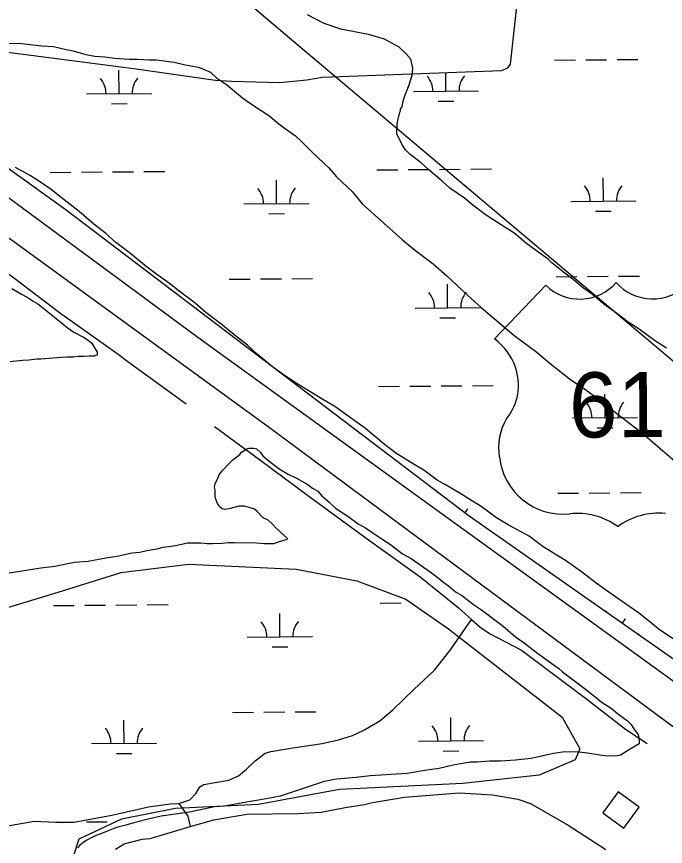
# Model space of a CAD drawing. Extents: x 3540316 to 3578335, y 553172 to 578787.
# Drawn here: x 3561395 to 3562392, y 561755 to 563030 of the extents above; entities that cross this region are included whole.
import ezdxf

# ---------------------------------------------------------------- set-up
doc = ezdxf.new("R2010")
doc.units = 0
for name, color, linetype in [('V-BLDG-OTLN', 7, 'Continuous'), ('V-ROAD-CNTR', 7, 'Continuous'), ('V-ROAD-IDEN', 7, 'Continuous'), ('V-SITE-VEGE', 7, 'Continuous'), ('V-TOPO-SHOR', 7, 'Continuous'), ('V-UTIL-LINE', 7, 'Continuous'), ('V-WETL-SWMP', 7, 'Continuous')]:
    doc.layers.add(name, color=color, linetype=linetype)

msp = doc.modelspace()

# ---------------------------------------------------------------- linework, layer by layer
at = {"layer": 'V-BLDG-OTLN'}
msp.add_lwpolyline([(3562351.7, 561815.5), (3562319.4, 561839), (3562295.8, 561806.7), (3562328.1, 561783.2)], close=True, dxfattribs=at)
at = {"layer": 'V-ROAD-CNTR'}
for points in [[(3562447.9, 561906.3), (3561783.8, 562398.2), (3561237.9, 562795), (3560747.4, 563166.4), (3559829.5, 563849.1), (3558932.4, 564513), (3557712.7, 565416.8), (3556649.6, 566203.3), (3555719, 566897), (3553740.9, 568356)], [(3561107.6, 562954.7), (3561673.7, 562537.4)], [(3561673.7, 562537.4), (3562657, 561826.3), (3562970.4, 561585), (3563229, 561375.2), (3563431.3, 561200.6), (3563553.8, 561106), (3563686, 560983.7)]]:
    msp.add_lwpolyline(points, dxfattribs=at)
at = {"layer": 'V-ROAD-IDEN'}
for q in [(3562208, 562617), (3562208, 562617), (3562129.5, 562534.7)]:
    msp.add_line((3562129.5, 562534.7), q, dxfattribs=at)
for centre, major_axis, start_param, end_param in [((3562260.2, 562670.8), (0.6, -75), 5.502702, 7.121811), ((3562260.2, 562670.8), (0.6, -75), 5.502702, 7.121811), ((3562372.2, 562671), (-0.6, 75), 2.291842, 3.917604), ((3562372.2, 562671), (-0.6, 75), 2.291842, 3.917604), ((3562074.7, 562460.5), (-0.7, 92.2), 5.045266, 5.638568), ((3562074.7, 562460.5), (-0.7, 92.2), 5.045266, 5.638568), ((3562084.8, 562463.7), (-0.6, 81.6), 4.021008, 5.049788), ((3562084.8, 562463.7), (-0.6, 81.6), 4.021008, 5.049788), ((3562221.9, 562367.6), (0.7, -86.5), 4.163028, 4.868958), ((3562221.9, 562367.6), (0.7, -86.5), 4.163028, 4.868958), ((3562234.8, 562364.2), (-0.8, 98.8), 1.672766, 3.238327), ((3562234.8, 562364.2), (-0.8, 98.8), 1.672766, 3.238327), ((3562256.7, 562161), (-0.8, 105.6), 5.646836, 6.385311), ((3562256.7, 562161), (-0.8, 105.6), 5.646836, 6.385311), ((3562381.4, 562161.3), (0.8, -105.6), 3.034929, 3.773404), ((3562381.4, 562161.3), (0.8, -105.6), 3.034929, 3.773404)]:
    msp.add_ellipse(centre, major_axis=major_axis, ratio=0.99789, start_param=start_param, end_param=end_param, dxfattribs=at)
at = {"layer": 'V-SITE-VEGE'}
for points in [[(3561985.2, 562884.9), (3561985.2, 562888.1), (3561987.4, 562891.3), (3561988.5, 562897.8), (3561990.7, 562905.3), (3561998.4, 562924.6), (3562002.8, 562939.6), (3562004, 562950.4), (3562000.9, 562964.4), (3561993.4, 562973), (3561982.7, 562982.8), (3561960.2, 562994.8), (3561937.7, 563001.4), (3561893.6, 563010.4), (3561867.9, 563019.2), (3561842.1, 563032.3)], [(3561327.6, 562988.8), (3561402.9, 562988.2), (3561434.1, 562984.8), (3561452.3, 562983.6), (3561471.7, 562979.1), (3561482.4, 562976.9), (3561501.7, 562971.4), (3561515.7, 562969.1), (3561530.8, 562967.9), (3561545.8, 562965.6), (3561568.4, 562964.4), (3561581.3, 562964.3), (3561599.6, 562963.1), (3561610.3, 562963), (3561637.2, 562959.6), (3561652.2, 562956.2), (3561663, 562954), (3561674.8, 562951.8), (3561683.4, 562948.5), (3561693, 562944.1), (3561702.6, 562935.4), (3561717.6, 562925.6), (3561742.2, 562905), (3561752.9, 562897.4), (3561771.1, 562885.4), (3561782.9, 562877.8), (3561797.9, 562864.8), (3561808.6, 562857.2), (3561823.5, 562846.3), (3561833.2, 562837.6), (3561848.1, 562822.5), (3561858.8, 562812.7), (3561874.8, 562797.5), (3561886.5, 562783.4), (3561911.1, 562760.7), (3561926, 562742.3), (3561988, 562686.9), (3562006.2, 562671.7), (3562035.1, 562650), (3562056.4, 562631.6), (3562088.5, 562601.2), (3562108.8, 562582.7), (3562159, 562540.4), (3562194.3, 562514.3), (3562214.7, 562497), (3562246.7, 562472), (3562269.2, 562456.8), (3562293.8, 562438.3), (3562319.5, 562418.7)], [(3562393.4, 562520.4), (3562375.2, 562532.3), (3562351.7, 562549.7), (3562334.5, 562560.6), (3562313.1, 562576.9), (3562299.2, 562586.7), (3562280, 562603), (3562266.1, 562612.8), (3562250, 562625.8), (3562237.2, 562635.6), (3562218, 562650.8), (3562211.6, 562657.3), (3562184.8, 562676.8), (3562178.4, 562681.2), (3562159.1, 562697.5), (3562145.2, 562706.2), (3562127, 562718.2), (3562115.2, 562725.8), (3562096, 562739.9), (3562083.2, 562750.8), (3562060.7, 562766), (3562048.9, 562776.8), (3562028.6, 562794.2), (3562016.9, 562805), (3561999.8, 562818.1), (3561992.3, 562825.7), (3561988, 562832.2), (3561983.8, 562839.7), (3561979.5, 562849.4), (3561979.7, 562864.5), (3561980.8, 562869.9), (3561984.1, 562882.7), (3561985.2, 562884.9)], [(3561429.3, 562777.2), (3561415.4, 562785.9), (3561393.9, 562797.9)], [(3562405.1, 562072.8), (3562382.6, 562088), (3562367.7, 562099.9), (3562350.6, 562114), (3562317.4, 562136.9), (3562285.3, 562159.7), (3562262.8, 562177.1), (3562238.2, 562194.5), (3562203.9, 562215.2), (3562182.5, 562231.5), (3562150.4, 562248.9), (3562132.2, 562259.8), (3562108.7, 562277.2), (3562091.5, 562288.1), (3562077.6, 562296.8), (3562055.1, 562309.9), (3562041.2, 562317.5), (3562020.9, 562332.8), (3562005.9, 562341.5), (3561978, 562358.9), (3561959.8, 562373), (3561931, 562396.9), (3561911.7, 562411), (3561883.9, 562430.6), (3561865.7, 562441.5), (3561849.6, 562451.3), (3561825, 562466.5), (3561806.8, 562478.5), (3561788.6, 562491.6), (3561765.1, 562511.1), (3561750.1, 562525.2), (3561726.6, 562543.7), (3561711.6, 562555.6), (3561686, 562575.2), (3561669.9, 562589.3), (3561645.3, 562607.7), (3561630.3, 562619.7), (3561608.9, 562634.9), (3561591.8, 562647.9), (3561568.3, 562667.5), (3561548, 562682.7), (3561532, 562696.8), (3561513.8, 562710.9), (3561491.3, 562730.5), (3561459.2, 562755.4), (3561448.6, 562764.1), (3561429.3, 562777.2)], [(3561388, 562612.1), (3561402.7, 562603.3), (3561411.9, 562598.6), (3561421, 562592.4), (3561428.2, 562588.3), (3561439.9, 562579.5), (3561448.5, 562572.2), (3561463.7, 562559.9), (3561472.9, 562552.1), (3561483.1, 562544.9), (3561498.3, 562537.1), (3561503.9, 562533.5), (3561510.5, 562528.8), (3561519.1, 562514.5), (3561519.1, 562509.9), (3561516.5, 562508.9), (3561514.5, 562507.9), (3561506.8, 562507.9), (3561499.1, 562507.5), (3561489.4, 562507.5), (3561482.8, 562506.6), (3561472.5, 562506.6), (3561463.8, 562506.2), (3561444.9, 562504.3), (3561432.6, 562503.4), (3561426.5, 562503.4), (3561414.2, 562502), (3561404.5, 562501.5), (3561385.6, 562499.6)], [(3562319.5, 562418.7), (3562356.9, 562389.4), (3562413.6, 562340.6)], [(3561736.7, 562277.8), (3561731.3, 562276.1), (3561721.5, 562273.5), (3561715.3, 562272.7), (3561711.7, 562273.6), (3561707.3, 562276.3), (3561705.5, 562279.8), (3561703.8, 562281.6), (3561702.9, 562284.3), (3561700.3, 562291.5), (3561700.4, 562302.1), (3561699.5, 562306.6), (3561700.5, 562312.8), (3561703.2, 562318.1), (3561706.8, 562327), (3561712.2, 562333.2), (3561721.1, 562342.9), (3561727.4, 562349.1), (3561738.2, 562357), (3561740.9, 562360.6), (3561748.9, 562365.8), (3561752.5, 562366.7), (3561759.6, 562366.7), (3561764, 562365.7), (3561770.2, 562360.3), (3561773.7, 562355), (3561780.8, 562348.7), (3561785.2, 562345.1), (3561794.1, 562338.8), (3561798.5, 562335.2), (3561812.7, 562327.1), (3561825.1, 562320.8), (3561842.8, 562310.9), (3561849.9, 562305.5), (3561857.9, 562301), (3561864.1, 562293.8), (3561875.6, 562283.9), (3561885.3, 562274.9), (3561903.9, 562262.3), (3561919.8, 562250.6), (3561931.3, 562244.3), (3561941.1, 562238), (3561957.9, 562226.3), (3561969.4, 562219.1), (3561988, 562204.7), (3562001.3, 562197.5), (3562030.5, 562176.8), (3562040.2, 562169.6), (3562051.7, 562160.7), (3562058.8, 562155.3), (3562069.4, 562146.3), (3562080.1, 562140), (3562096.9, 562126.5)], [(3561380.8, 562174.6), (3561432.5, 562183.1), (3561453.9, 562185.6), (3561484.2, 562191.6), (3561505.5, 562193.2), (3561532.3, 562198.4), (3561550.1, 562200.9), (3561572.4, 562206.1), (3561584.8, 562206.9), (3561595.5, 562209.5), (3561610.7, 562212), (3561620.5, 562214.6), (3561633, 562216.3), (3561641.9, 562218), (3561653.5, 562220.6), (3561657.9, 562221.5), (3561678.4, 562221.3), (3561688.2, 562220.3), (3561696.2, 562220.3), (3561711.3, 562221.1), (3561720.2, 562221.9), (3561730, 562221.8), (3561763.8, 562221.6), (3561775.4, 562220.6), (3561790.5, 562220.5), (3561797.7, 562223.1), (3561805.7, 562225.7), (3561809.3, 562226.6), (3561811.9, 562227.4), (3561793.4, 562244.5), (3561788.1, 562250.7), (3561781.9, 562256.1), (3561773.9, 562259.8), (3561765.1, 562269.6), (3561760.7, 562273.2), (3561752.7, 562275.9), (3561745.6, 562277.8), (3561736.7, 562277.8)], [(3562096.9, 562126.5), (3562109.3, 562118.4), (3562142.9, 562093.2), (3562161.5, 562077.1), (3562174.8, 562068.1), (3562193.3, 562053.7), (3562206.6, 562043.8), (3562227.9, 562028.5), (3562234, 562023.1), (3562254.4, 562007.8), (3562266.8, 561998), (3562283.6, 561985.4), (3562293.3, 561977.3), (3562308.4, 561967.4), (3562318.1, 561959.3), (3562327.9, 561952.1), (3562333.2, 561948.5), (3562339.3, 561942.2), (3562344.6, 561934.2), (3562349.9, 561927), (3562350.8, 561922.6), (3562351.6, 561915.4), (3562351.6, 561912.8), (3562339.1, 561905.7), (3562323, 561895.2), (3562317.6, 561894.3), (3562302.5, 561893.6), (3562290.9, 561895.4), (3562272.3, 561898.2), (3562258.9, 561900.1), (3562237.6, 561900.3), (3562219.8, 561897.7), (3562185.9, 561890), (3562161.8, 561887.5), (3562138.7, 561885.9), (3562121.8, 561886), (3562102.2, 561884.4), (3562092.4, 561884.5), (3562077.2, 561881.9), (3562065.7, 561880.2), (3562044.3, 561875), (3562025.6, 561872.5), (3561995.3, 561867.4), (3561938.3, 561863.4), (3561916.9, 561860.9), (3561886.6, 561858.4), (3561867.9, 561855), (3561849.2, 561848.9), (3561818.8, 561838.5), (3561800.1, 561832.4), (3561778.7, 561828.1), (3561743, 561822.1), (3561714.5, 561817), (3561699.4, 561816.2), (3561661.1, 561807.6), (3561617.4, 561801.7), (3561599.6, 561797.4), (3561575.5, 561791.3), (3561563, 561787.9), (3561548.8, 561784.4), (3561536.2, 561779.2), (3561527.3, 561775.7), (3561517.5, 561772.2), (3561512.1, 561769.6), (3561502.3, 561764.3), (3561497, 561760.8), (3561492.5, 561757.2), (3561488.9, 561752.8)]]:
    msp.add_lwpolyline(points, dxfattribs=at)
at = {"layer": 'V-TOPO-SHOR'}
for points in [[(3561255.4, 562728.8), (3561316.3, 562683.2), (3561392.8, 562627.5), (3561461.5, 562575.1), (3561551.2, 562511.2), (3561566.4, 562500.1), (3561655.7, 562435.1)], [(3561699.2, 562400.1), (3561768.6, 562349.6), (3561846.3, 562291.6), (3561934, 562227.7), (3562015.3, 562169.1), (3562073.4, 562122.2), (3562094, 562103.6), (3562106.9, 562092.5), (3562121.7, 562082), (3562170.8, 562056.6), (3562273.1, 561979.7), (3562330.5, 561935.4), (3562363.7, 561913.1)], [(3561378.7, 561786.2), (3561422.5, 561794), (3561466.3, 561791.8), (3561483.9, 561792.6), (3561541.7, 561803), (3561598.1, 561816.1), (3561631.5, 561820.8), (3561644.6, 561821.2), (3561661.4, 561826.5), (3561671.4, 561837.2), (3561676.8, 561846.6), (3561683.2, 561850.2), (3561697.2, 561852.8), (3561721.6, 561857.1), (3561736, 561863.8), (3561748.7, 561874), (3561761.9, 561886.6), (3561777.3, 561898.2), (3561785.9, 561900.8), (3561819.8, 561906.4), (3561864.9, 561913.3), (3561889.8, 561919), (3561911.5, 561925.6), (3561927.8, 561933.1), (3561953.1, 561947.8), (3561973.1, 561964.8), (3562005.4, 561996.1), (3562037.2, 562026.1), (3562061.7, 562057.1), (3562094, 562103.6)], [(3561600.6, 561767.2), (3561662.2, 561785.6), (3561698.3, 561795.9), (3561749.2, 561804.6), (3561827.1, 561805.6), (3561863.2, 561807.8), (3561900.1, 561814.9), (3561929.7, 561819.6), (3561942, 561822.8), (3561991.2, 561830.6), (3562074.9, 561837.4), (3562126.5, 561834.5), (3562165, 561827.7), (3562184.6, 561821), (3562242.6, 561787.8), (3562300.5, 561750.4)], [(3561644.6, 561821.2), (3561658.5, 561801.7), (3561662.2, 561785.6)], [(3561547.2, 561751.2), (3561560.4, 561759.3), (3561588.3, 561766.4), (3561600.6, 561767.2)]]:
    msp.add_lwpolyline(points, dxfattribs=at)
at = {"layer": 'V-UTIL-LINE'}
msp.add_lwpolyline([(3556955.2, 567075.4), (3557124.3, 566919.9), (3558248.1, 566016.7), (3559018.6, 565342.7), (3559967, 564552.1), (3561006.7, 563681.5), (3561821.4, 562991.2), (3562900.8, 562082.4), (3563540.2, 561550.9), (3563866.3, 561304.1)], dxfattribs=at)
at = {"layer": 'V-WETL-SWMP'}
for p, q in [((3562154, 562956.4), (3562170.4, 563107.7)), ((3561107, 563010.2), (3561578.8, 562949.6)), ((3561471.6, 562732.4), (3561100, 562999.1)), ((3562317.5, 562963.6), (3562349.5, 562963.9)), ((3562149.8, 562950.9), (3562154, 562956.4)), ((3562221.5, 562962.9), (3562253.5, 562963.1)), ((3562269.5, 562963.3), (3562301.5, 562963.5)), ((3561552.9, 562911.3), (3561552.6, 562947.3)), ((3561578.8, 562949.6), (3561701, 562932.1)), ((3561864.9, 562936.4), (3562140, 562946.8)), ((3562054.8, 562915.2), (3562054.5, 562943.5)), ((3562140, 562946.8), (3562149.8, 562950.9)), ((3561701, 562932.1), (3561725.9, 562930.5)), ((3561725.9, 562930.5), (3561799.6, 562928.5)), ((3561799.6, 562928.5), (3561841.3, 562932.4)), ((3561841.3, 562932.4), (3561864.9, 562936.4)), ((3562004.8, 562914.8), (3562104.8, 562915.6)), ((3561502.9, 562910.9), (3561602.9, 562911.7)), ((3561541, 562895.8), (3561565, 562896)), ((3562042.9, 562899.6), (3562066.9, 562899.8)), ((3561447, 562790.4), (3561478.9, 562790.7)), ((3561494.9, 562790.8), (3561526.9, 562791)), ((3561542.9, 562791.2), (3561574.9, 562791.4)), ((3561590.9, 562791.5), (3561622.9, 562791.8)), ((3561948.8, 562794.3), (3561980.8, 562794.5)), ((3561996.8, 562794.6), (3562028.8, 562794.9)), ((3562044.8, 562795), (3562076.8, 562795.3)), ((3562092.8, 562795.4), (3562124.8, 562795.6)), ((3561794.6, 562742.3), (3561794.4, 562778.3)), ((3562296.5, 562746.2), (3562296.3, 562782.2)), ((3561744.6, 562742), (3561844.6, 562742.7)), ((3562246.5, 562745.8), (3562346.5, 562746.6)), ((3562090.4, 562262.3), (3561471.6, 562732.4)), ((3561782.8, 562726.8), (3561806.8, 562727)), ((3562284.7, 562730.7), (3562308.7, 562730.9)), ((3561722.1, 562626.4), (3561754.1, 562626.6)), ((3561770.1, 562626.7), (3561802.1, 562627)), ((3561818.1, 562627.1), (3561850.1, 562627.3)), ((3562224, 562630.2), (3562256, 562630.5)), ((3562272, 562630.6), (3562304, 562630.8)), ((3562320, 562631), (3562352, 562631.2)), ((3562057.3, 562582.5), (3562057, 562618.5)), ((3562007.3, 562582.1), (3562107.3, 562582.9)), ((3562045.4, 562567), (3562069.4, 562567.2)), ((3561951.4, 562461.6), (3561983.4, 562461.9)), ((3561999.4, 562462), (3562031.4, 562462.2)), ((3562047.4, 562462.4), (3562079.4, 562462.6)), ((3562095.4, 562462.7), (3562127.4, 562463)), ((3562299.1, 562413.6), (3562298.8, 562449.6)), ((3562249.1, 562413.2), (3562349.1, 562413.9)), ((3562287.2, 562398), (3562311.2, 562398.2)), ((3562226.6, 562297.6), (3562258.6, 562297.8)), ((3562274.6, 562297.9), (3562306.6, 562298.2)), ((3562322.6, 562298.3), (3562354.6, 562298.5)), ((3562059.6, 562285.7), (3562059.6, 562285.8)), ((3562557.4, 561935.1), (3562090.4, 562262.3)), ((3562107.7, 562250.2), (3562109.9, 562250.2)), ((3561452, 562125.1), (3561484, 562125.4)), ((3561500, 562125.5), (3561532, 562125.7)), ((3561548, 562125.9), (3561580, 562126.1)), ((3561596, 562126.2), (3561628, 562126.5)), ((3561953.9, 562129), (3561985.9, 562129.2)), ((3561799.7, 562077.1), (3561799.5, 562113.1)), ((3562301.4, 562114.5), (3562301.4, 562116.9)), ((3561749.7, 562076.7), (3561849.7, 562077.4)), ((3562348.8, 562081.2), (3562351.7, 562081.3)), ((3561787.9, 562061.5), (3561811.9, 562061.7)), ((3561727.2, 561961.1), (3561759.2, 561961.3)), ((3561775.2, 561961.4), (3561807.2, 561961.7)), ((3561823.2, 561961.8), (3561855.2, 561962)), ((3561560.5, 561913.3), (3561560.3, 561949.3)), ((3562062.4, 561917.2), (3562062.1, 561953.2)), ((3561510.5, 561913), (3561610.5, 561913.7)), ((3562012.4, 561916.8), (3562112.4, 561917.6)), ((3561548.6, 561897.8), (3561572.6, 561898)), ((3562050.5, 561901.7), (3562074.5, 561901.9)), ((3561454.6, 561792.5), (3561486.6, 561792.7)), ((3561502.6, 561792.8), (3561534.6, 561793.1))]:
    msp.add_line(p, q, dxfattribs=at)
msp.add_lwpolyline([(3561359.3, 562115.4), (3561459.5, 562145.7), (3561556.2, 562175.9), (3561659.6, 562188.9), (3561824.9, 562180.8), (3561917.8, 562162.9), (3561993.4, 562134.7), (3562058.5, 562089.5), (3562233.2, 561953.8), (3562260.4, 561905.3), (3562253.4, 561888.2), (3562198.1, 561864.5), (3562080.8, 561851.6), (3561891.3, 561842.7), (3561767.1, 561819.5), (3561639.6, 561813.6), (3561556.7, 561797), (3561491.1, 561766.5), (3561466.4, 561690.9), (3561468.9, 561566.8), (3561478.3, 560991.4), (3561471.2, 560970.8), (3561440.2, 560964.1), (3561392.2, 560992.1)], dxfattribs=at)
for centre, start, end in [((3561999.5, 562915.2), 359.6699, 41.2135), ((3562110, 562916.1), 139.6699, 181.2135), ((3561497.6, 562911.4), 359.6699, 41.2135), ((3561608.1, 562912.2), 139.6699, 181.2135), ((3561739.4, 562742.4), 359.6699, 41.2135), ((3561849.9, 562743.2), 139.6699, 181.2135), ((3562241.3, 562746.3), 359.6699, 41.2135), ((3562351.8, 562747.1), 139.6699, 181.2135), ((3562002.1, 562582.6), 359.6699, 41.2135), ((3562112.6, 562583.4), 139.6699, 181.2135), ((3562243.9, 562413.6), 359.6699, 41.2135), ((3562354.3, 562414.5), 139.6699, 181.2135), ((3562115.1, 562250.7), 139.6699, 152.1516), ((3561744.5, 562077.1), 359.6699, 41.2135), ((3561855, 562078), 139.6699, 181.2135), ((3562356.9, 562081.8), 139.6699, 153.2446), ((3561505.3, 561913.4), 359.6699, 41.2135), ((3561615.8, 561914.2), 139.6699, 181.2135), ((3562007.2, 561917.3), 359.6699, 41.2135), ((3562117.7, 561918.1), 139.6699, 181.2135)]:
    msp.add_arc(centre, 35.2, start, end, dxfattribs=at)

# ---------------------------------------------------------------- texts
at = {"layer": 'V-ROAD-IDEN'}
msp.add_text('61', height=100, rotation=0.4506, dxfattribs=at).set_placement((3562244.1, 562383))

doc.saveas('drawing.dxf')
